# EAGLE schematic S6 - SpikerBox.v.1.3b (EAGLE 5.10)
DIGIKEY: LM386N-3-ND; MANUFACTURER: NATIONAL SEMICONDUCTOR; PARTNO: K474Z20Y5VE5TL2
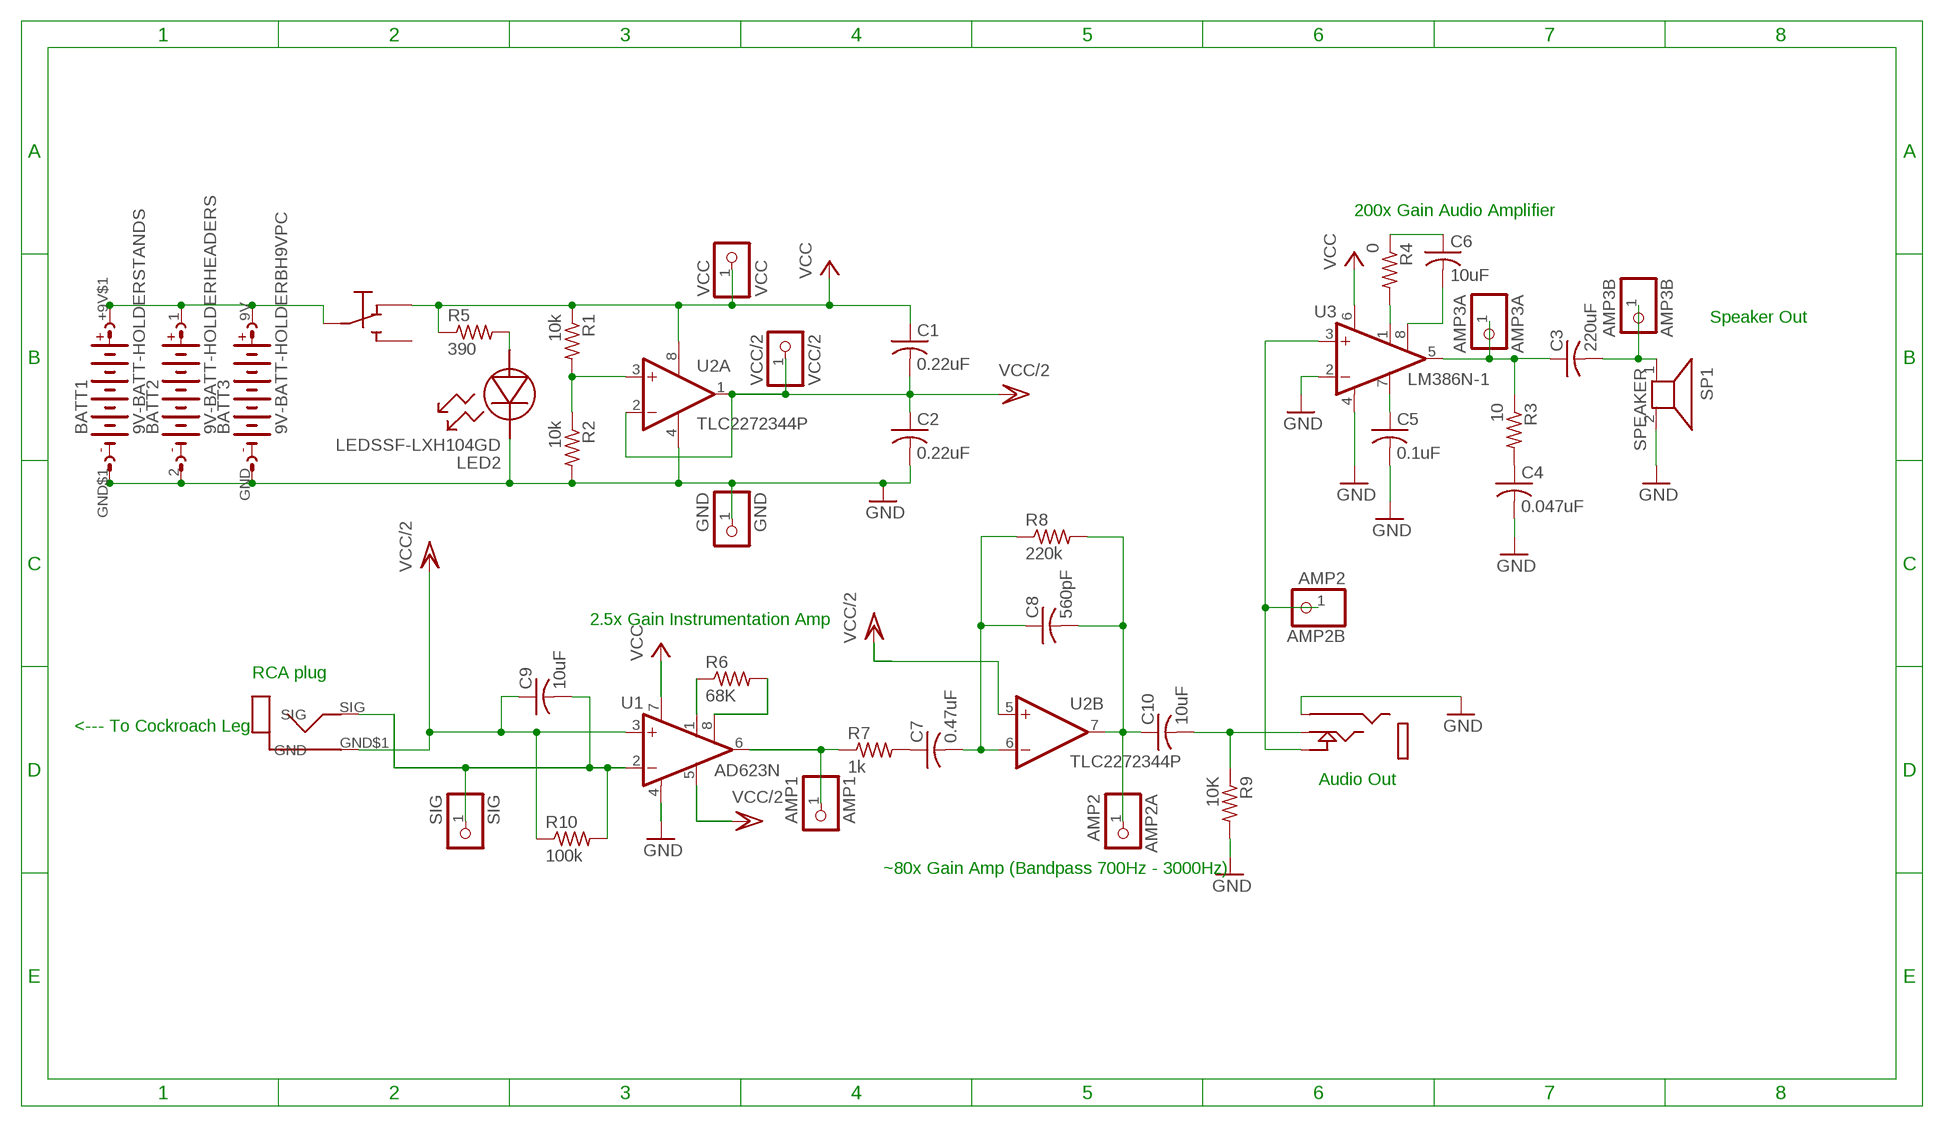
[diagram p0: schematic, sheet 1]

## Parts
AMP1  AMP1  PINHD-1X1  [1X01]
AMP2A  AMP2  PINHD-1X1  [1X01]
AMP2B  AMP2  PINHD-1X1  [1X01]
AMP3A  AMP3A  PINHD-1X1  [1X01]
AMP3B  AMP3B  PINHD-1X1  [1X01]
BATT1  9V-BATT-HOLDERSTANDS  [KEYSTONE-593-594]
BATT2  9V-BATT-HOLDERHEADERS  [1X02]
BATT3  9V-BATT-HOLDERBH9VPC  [BH9VPC]
C1  0.22uF  C-US050-024X044  [C050-024X044]
C2  0.22uF  C-US050-024X044  [C050-024X044]
C3  220uF  C-US050-050X075  [C050-050X075]
C4  0.047uF  C-US050-024X044  [C050-024X044]
C5  0.1uF  C-US050-024X044  [C050-024X044]
C6  10uF  C-US050-030X075  [C050-030X075]
C7  0.47uF  C-US050-024X044  [C050-024X044]
C8  560pF  C-US050-024X044  [C050-024X044]
C9  10uF  C-US050-030X075  [C050-030X075]
C10  10uF  C-US050-030X075  [C050-030X075]
GND  GND  PINHD-1X1  [1X01]
J1  RCA  [RCJ]
J2  AUD  AUDIOJACK3.5MM  [AUDIO-JACK]
LED2  LEDSSF-LXH104GD  [SSF-LXH104GD]
R1  10k  R-US_0207/10  [0207/10]
R2  10k  R-US_0207/10  [0207/10]
R3  10  R-US_0207/10  [0207/10]
R4  0  R-US_0207/10  [0207/10]
R5  390  R-US_0207/10  [0207/10]
R6  68K  R-US_0207/10  [0207/10]
R7  1k  R-US_0207/10  [0207/10]
R8  220k  R-US_0207/10  [0207/10]
R9  10K  R-US_0207/10  [0207/10]
R10  100k  R-US_0207/10  [0207/10]
SIG  SIG  PINHD-1X1  [1X01]
SP1  SPEAKER  [1X02]
SW1  SPDT Switch  2M1-SP1-T2-B4-M6RE  [2M1-SP1-T2-B4-M6RE]
U1  AD623N  [DIL08]
U2  TLC2272344P  [DIL08]
U3  LM386N-1  [DIL08]
VCC  VCC  PINHD-1X1  [1X01]
VCC/2  VCC/2  PINHD-1X1  [1X01]

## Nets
GND: BATT1.GND$1(-) BATT2.2(-) BATT3.GND(-) C2.2 C4.2 C5.2 GND.1 J2.1(SHIELD) LED2.CATHODE R2.2 R9.2 SP1.2 U1.4(GND) U2.4(A:V-) U3.2(-IN) U3.4(GND)
IN-: C9.2 J1.SIG R10.2 SIG.1 U1.2(-IN)
N$2: AMP3B.1 C3.2 SP1.1
N$3: AMP1.1 R7.1 U1.6(OUT)
N$4: C10.2 J2.2(INPUTA) R9.1
N$6: C4.1 R3.2
N$7: AMP3A.1 C3.1 R3.1 U3.5(OUT)
N$8: C5.1 U3.7(BYPASS)
N$10: C6.1 R4.1
N$11: R4.2 U3.1(GAIN)
N$12: C6.2 U3.8(GAIN)
N$14: LED2.ANODE R5.2
N$15: R6.1 U1.1(GAIN)
N$18: R6.2 U1.8(GAIN)
N$19: C7.1 R7.2
N$20: C7.2 C8.1 R8.1 U2.6(B:-IN)
N$24: R1.2 R2.1 U2.3(A:+IN)
N$28: AMP2B.1 J2.4(SPEAKEROUT) U3.3(+IN)
N$29: AMP2A.1 C8.2 C10.1 R8.2 U2.7(B:OUT)
V9HOT: BATT1.+9V$1(+) BATT2.1(+) BATT3.9V(+) SW1.P2
VCC: C1.1 R1.1 R5.1 SW1.P3 U1.7(VS) U2.8(A:V+) U3.6(VS) VCC.1
VCC/2: C1.2 C2.1 C9.1 J1.GND$1(GND) R10.1 U1.3(+IN) U1.5(BYPASS) U2.1(A:OUT) U2.2(A:-IN) U2.5(B:+IN) VCC/2.1
Unconnected: SW1.P1

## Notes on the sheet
- 200x Gain Audio Amplifier
- Speaker Out
- 2.5x Gain Instrumentation Amp
- RCA plug
- <--- To Cockroach Leg
- Audio Out
- ~80x Gain Amp (Bandpass 700Hz - 3000Hz)

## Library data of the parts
AMP1 AMP2A AMP2B AMP3A AMP3B GND SIG VCC VCC/2 = pinhead:PINHD-1X1: PIN HEADER
BATT1-BATT3 = byb:9V-BATT-HOLDER
C1-C10 = resistor:C-US: CAPACITOR, American symbol
J1 = byb:RCA
J2 = byb:AUDIOJACK: 1/8" Audio Jack
LED2 = byb:LED: SIDE LED (Green)
R1-R10 = rcl:R-US_: RESISTOR, American symbol
SP1 = byb:SPEAKER: SPEAKER
SW1 = byb:2M1-SP1-T2-B4-M6RE: Toggle Switch
U1 = byb:AD623: Instrumentation Amp Single-Power, Low Cost, Instrumentation Amp
U2 = byb:TLC2272: Dual Operational Amplifier Low Power, Single-Supply, Rail-To-Rail Operational Amplifier Source: http://focus.ti.com/lit/ds/symlink/opa2345.pdf http://focus.ti.com .. opa241.pdf http://focus.ti.com/lit/ds/symlink/opa2134.pdf
U3 = byb:LM386?-*: Low Voltage Audio Power Amplifier Source: http://cache.national.com/ds/LM/LM386.pdf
